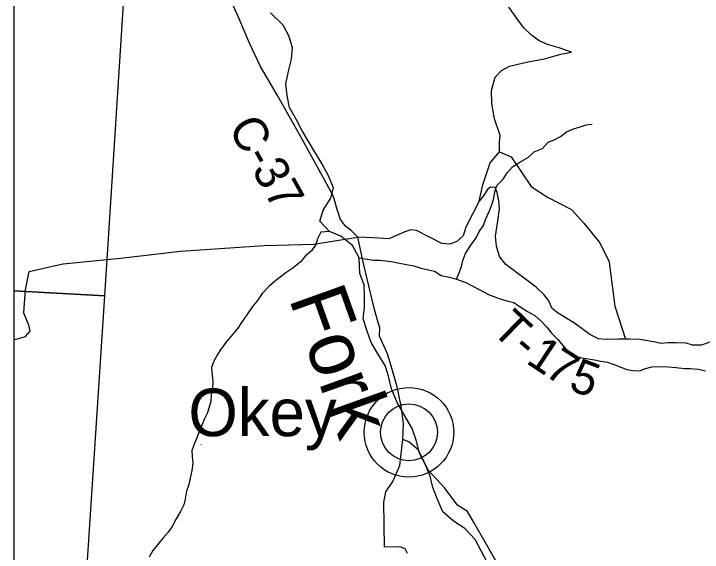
# Model space of a CAD drawing. Extents: x 396.2 to 468.4, y 232.6 to 279.1.
# Drawn here: x 413.851 to 414.996, y 267.141 to 268.036 of the extents above; entities that cross this region are included whole.
import ezdxf

# ---------------------------------------------------------------- set-up
doc = ezdxf.new("R2010")
doc.units = 0
for name, color, linetype in [('Default', 7, 'Continuous'), ('GM_X_County_Road', 7, 'Continuous'), ('GM_X_County_Road_Text', 7, 'Continuous'), ('GM_X_Minor_River', 7, 'Continuous'), ('GM_X_Minor_River_Text', 7, 'Continuous'), ('GM_X_Township_Road', 7, 'Continuous'), ('GM_X_Township_Road_Text', 7, 'Continuous'), ('GM_X_Unincorporated', 7, 'Continuous'), ('GM_X_Unincorporated_Location', 7, 'Continuous'), ('GM_X_Unincorporated_Text', 7, 'Continuous'), ('SH_Cut_Line', 7, 'Continuous'), ('TX_P_1', 7, 'Continuous')]:
    doc.layers.add(name, color=color, linetype=linetype)

msp = doc.modelspace()

# ---------------------------------------------------------------- linework, layer by layer
at = {"layer": 'Default'}
for points in [[(413.8513, 270.6726), (413.8513, 264.4868), (414.0592, 264.474), (414.3542, 264.4559), (414.8754, 264.4239), (414.9163, 265.108), (414.9927, 266.2714), (414.9935, 266.2891), (414.9982, 266.4735), (415.0293, 266.9964), (415.0582, 267.4588), (415.0934, 268.0402), (415.1765, 269.4523), (415.2459, 270.5284), (415.2492, 270.5871), (414.466, 270.6401), (414.1359, 270.6553), (413.8849, 270.6706)], [(413.8513, 268.6118), (413.8513, 267.5757), (414.0029, 267.5669), (414.0685, 268.5986)], [(413.8513, 267.5757), (413.8513, 266.5578), (413.936, 266.5526), (414.0029, 267.5669)]]:
    msp.add_lwpolyline(points, close=True, dxfattribs=at)
at = {"layer": 'GM_X_County_Road'}
msp.add_lwpolyline([(414.5058, 267.1388), (414.5019, 267.1464), (414.4928, 267.1501), (414.4678, 267.1496), (414.4666, 267.2244), (414.4696, 267.2414), (414.4813, 267.2586), (414.4929, 267.2849), (414.498, 267.3281), (414.499, 267.3547), (414.4954, 267.3839), (414.4884, 267.4158), (414.4784, 267.451), (414.4726, 267.4707), (414.4668, 267.4832), (414.4592, 267.4999), (414.4599, 267.5139), (414.4552, 267.5283), (414.4502, 267.5469), (414.4324, 267.6208), (414.4235, 267.6644), (414.4116, 267.6764), (414.4029, 267.6832), (414.3945, 267.6942), (414.3887, 267.7105), (414.3826, 267.7321), (414.368, 267.7601), (414.3286, 267.8312), (414.2896, 267.9001), (414.2616, 267.9481), (414.2433, 267.9871), (414.2225, 268.0352), (414.2091, 268.0647)], dxfattribs=at)
at = {"layer": 'GM_X_Minor_River'}
for points in [[(414.6417, 267.1181), (414.6289, 267.1424), (414.6183, 267.1621), (414.601, 267.1803), (414.5821, 267.1924), (414.5647, 267.2084), (414.5564, 267.2273), (414.5481, 267.2486), (414.5436, 267.2675), (414.536, 267.2865), (414.5255, 267.3055), (414.5202, 267.3275), (414.5134, 267.3464), (414.4892, 267.3889), (414.4794, 267.4124), (414.4742, 267.4336), (414.4689, 267.4511), (414.4576, 267.4693), (414.4455, 267.4898), (414.4387, 267.5087), (414.4319, 267.5292), (414.4342, 267.5482), (414.4342, 267.5664), (414.4335, 267.5853), (414.4267, 267.6043), (414.4252, 267.6301), (414.4146, 267.6506), (414.395, 267.6665), (414.3761, 267.6741), (414.3602, 267.6915), (414.3655, 267.7097), (414.3784, 267.7294), (414.383, 267.7469), (414.3747, 267.7666), (414.3634, 267.7871), (414.3407, 267.825), (414.3301, 267.8425), (414.3211, 267.8599), (414.3098, 267.8804), (414.306, 267.9001), (414.3037, 267.9198), (414.3083, 267.9426), (414.3129, 267.9608), (414.3144, 267.9797), (414.3084, 267.9995), (414.2993, 268.0169), (414.2782, 268.0374)], [(414.5871, 267.5951), (414.5913, 267.6045), (414.5955, 267.6159), (414.5978, 267.6258), (414.6023, 267.6375), (414.6111, 267.6511), (414.6198, 267.6633), (414.6251, 267.6739), (414.6319, 267.6841), (414.6357, 267.6939), (414.6414, 267.7076), (414.6468, 267.7201), (414.6494, 267.7295), (414.6509, 267.7398), (414.6544, 267.7508), (414.665, 267.761), (414.6714, 267.7716), (414.6805, 267.7818), (414.6926, 267.7894), (414.7067, 267.7977), (414.7165, 267.8064), (414.7301, 267.812), (414.7396, 267.8223), (414.7495, 267.8264), (414.7601, 267.8321), (414.7699, 267.8397), (414.7816, 267.8446), (414.793, 267.8483), (414.8028, 267.8514), (414.8127, 267.8525)], [(414.3761, 267.6741), (414.3618, 267.6731), (414.3561, 267.6621), (414.3534, 267.6523), (414.3462, 267.642), (414.3364, 267.6337), (414.3277, 267.6239), (414.3152, 267.6129), (414.3034, 267.6053), (414.2898, 267.5948), (414.2761, 267.583), (414.2644, 267.5713), (414.2564, 267.5596), (414.2481, 267.5497), (414.2386, 267.5357), (414.231, 267.5243), (414.2238, 267.5134), (414.2155, 267.5035), (414.206, 267.4922), (414.1954, 267.4785), (414.1893, 267.4687), (414.184, 267.4585), (414.1802, 267.4478), (414.1813, 267.4357), (414.182, 267.424), (414.1817, 267.4134), (414.1797, 267.4031), (414.179, 267.3914), (414.1763, 267.3819), (414.1729, 267.3717), (414.1676, 267.3615), (414.1509, 267.3192)], [(414.4252, 267.6301), (414.4389, 267.6279), (414.4495, 267.6267), (414.4593, 267.6263), (414.4692, 267.6252), (414.4794, 267.624), (414.4926, 267.6217), (414.5043, 267.6195), (414.5161, 267.6168), (414.5285, 267.613), (414.5406, 267.6103), (414.5505, 267.608), (414.5618, 267.6008), (414.5758, 267.5981), (414.5871, 267.5951), (414.6026, 267.5894), (414.6132, 267.5837), (414.6261, 267.5772), (414.6404, 267.5696), (414.6563, 267.5631), (414.6711, 267.5586), (414.6828, 267.5559), (414.6945, 267.5479), (414.7055, 267.5411), (414.7176, 267.5346), (414.7281, 267.5251), (414.7376, 267.5149), (414.7455, 267.5046), (414.7557, 267.4944), (414.7644, 267.4838), (414.7731, 267.4735), (414.7852, 267.4671), (414.7961, 267.464), (414.8166, 267.4609), (414.8271, 267.4587), (414.8381, 267.4567), (414.8479, 267.4537), (414.8604, 267.4484), (414.8702, 267.4449), (414.8812, 267.443), (414.8914, 267.4423), (414.9017, 267.4464), (414.9122, 267.4491), (414.9247, 267.4498), (414.9395, 267.4494), (414.9524, 267.4482), (414.966, 267.4463), (414.9758, 267.4463), (414.9894, 267.4455), (415.0011, 267.4425)], [(414.1509, 267.3192), (414.1509, 267.3192), (414.1471, 267.3098), (414.1479, 267.3003), (414.149, 267.2889), (414.1472, 267.2768), (414.1445, 267.2639), (414.1423, 267.2537), (414.1385, 267.2427), (414.1362, 267.2294), (414.134, 267.2195), (414.1283, 267.2085), (414.1211, 267.1964), (414.1151, 267.1847), (414.1079, 267.1744), (414.0996, 267.1649), (414.0905, 267.1532), (414.0822, 267.1437), (414.0765, 267.1327)], [(414.1626, 267.3194), (414.1622, 267.3198)]]:
    msp.add_lwpolyline(points, dxfattribs=at)
at = {"layer": 'GM_X_Township_Road'}
for points in [[(414.625, 267.7247), (414.6308, 267.7517), (414.6432, 267.7882), (414.6586, 267.8065), (414.6586, 267.8218), (414.66, 267.8335), (414.6505, 267.8612), (414.6462, 267.8868), (414.6454, 267.9087), (414.6513, 267.9306), (414.6622, 267.9415), (414.6754, 267.9488), (414.706, 267.9561), (414.7338, 267.9613), (414.7608, 267.9686), (414.7783, 267.9722), (414.7581, 267.9795), (414.7383, 267.9848), (414.7244, 267.9908), (414.7118, 268.0007), (414.6993, 268.0126), (414.69, 268.0252), (414.6741, 268.047)], [(414.6586, 267.8065), (414.678, 267.798), (414.7115, 267.7488), (414.7384, 267.7309), (414.7786, 267.7108), (414.7988, 267.6879), (414.8256, 267.6554), (414.8412, 267.6236), (414.8429, 267.6097)], [(414.8719, 267.4949), (414.8681, 267.4949), (414.8565, 267.4949), (414.8361, 267.4944), (414.8235, 267.4955), (414.8091, 267.503), (414.7832, 267.5215), (414.7551, 267.5391), (414.7459, 267.5467), (414.7406, 267.5588), (414.7329, 267.569), (414.7196, 267.5818), (414.669, 267.6191), (414.6587, 267.6327), (414.6537, 267.6498), (414.6521, 267.6665), (414.6557, 267.6919), (414.659, 267.7117), (414.6578, 267.7253), (414.6547, 267.739), (414.6517, 267.7473), (414.6437, 267.748), (414.6388, 267.7438), (414.6316, 267.7327), (414.625, 267.7247), (414.6027, 267.6813), (414.5986, 267.6669), (414.5877, 267.6574), (414.5763, 267.6531), (414.5627, 267.6542), (414.5205, 267.6759), (414.5114, 267.677), (414.5011, 267.6735), (414.4747, 267.662), (414.4485, 267.6638), (414.4235, 267.6644)], [(413.9254, 267.6185), (413.9336, 267.6204), (414.029, 267.6299), (414.1283, 267.6413), (414.2677, 267.6509), (414.3498, 267.6528), (414.4235, 267.6644)], [(413.8682, 267.5381), (413.8678, 267.5392), (413.8709, 267.5772), (413.8767, 267.6075), (413.9254, 267.6185)], [(414.8429, 267.6097), (414.8502, 267.5498), (414.8681, 267.4949)], [(413.8513, 267.4938), (413.8707, 267.4993), (413.8787, 267.5087), (413.8761, 267.5183), (413.8753, 267.5209), (413.8682, 267.5381)], [(415.0584, 267.4583), (415.0421, 267.4649), (415.0337, 267.4762), (415.0222, 267.4895), (415.0135, 267.4917), (414.9942, 267.4851), (414.9798, 267.485), (414.9692, 267.4884), (414.9525, 267.489), (414.9392, 267.489), (414.9275, 267.4881), (414.9149, 267.4907), (414.8922, 267.4948), (414.8748, 267.4949), (414.8719, 267.4949)], [(414.8616, 266.822), (414.863, 266.8413), (414.8629, 266.8565), (414.8605, 266.8683), (414.8537, 266.877), (414.8427, 266.8961), (414.838, 266.9043), (414.8076, 266.9797), (414.7865, 267.0203), (414.7654, 267.0555), (414.7361, 267.0878), (414.7198, 267.1002), (414.7012, 267.108), (414.6587, 267.1162), (414.6154, 267.1914), (414.6055, 267.2085), (414.5891, 267.219), (414.5678, 267.2473), (414.5399, 267.2772), (414.5242, 267.3108), (414.5082, 267.3244), (414.498, 267.3281)]]:
    msp.add_lwpolyline(points, dxfattribs=at)
at = {"layer": 'GM_X_Unincorporated'}
for radius in [0.0744, 0.0472]:
    msp.add_circle((414.5082, 267.3403), radius, dxfattribs=at)
at = {"layer": 'GM_X_Unincorporated_Location'}
msp.add_line((414.5082, 267.3403), (414.5082, 267.3403), dxfattribs=at)
at = {"layer": 'SH_Cut_Line'}
msp.add_lwpolyline([(413.8513, 270.6726), (413.8513, 264.2582), (416.1109, 264.2582), (415.3533, 264.289), (414.8684, 264.3083), (414.8754, 264.4239), (414.9163, 265.108), (414.9927, 266.2714), (414.9935, 266.2891), (414.9982, 266.4735), (415.0293, 266.9964), (415.0582, 267.4588), (415.0934, 268.0402), (415.1765, 269.4523), (415.2459, 270.5284), (415.2492, 270.5871), (414.466, 270.6401), (414.1359, 270.6553), (413.8849, 270.6706)], close=True, dxfattribs=at)
at = {"layer": 'TX_P_1'}
msp.add_line((413.8513, 277.8582), (413.8513, 264.2582), dxfattribs=at)

# ---------------------------------------------------------------- texts
at = {"layer": 'GM_X_County_Road_Text'}
msp.add_text('C-37', height=0.05682, rotation=299.1887, dxfattribs=at).set_placement((414.2069, 267.847))
at = {"layer": 'GM_X_Minor_River_Text'}
msp.add_text('Fork', height=0.09469, rotation=289.6605, dxfattribs=at).set_placement((414.308, 267.5632))
at = {"layer": 'GM_X_Township_Road_Text'}
for s, rotation, p in [('T', 315.9016, (414.6436, 267.5083)), ('-', 319.7622, (414.6772, 267.4759)), ('1', 326.4872, (414.7008, 267.4565)), ('7', 327.3258, (414.7308, 267.4367)), ('5', 339.0958, (414.7716, 267.412))]:
    msp.add_text(s, height=0.0568, rotation=rotation, dxfattribs=at).set_placement(p)
at = {"layer": 'GM_X_Unincorporated_Text'}
msp.add_text('Okey', height=0.07898, rotation=0, dxfattribs=at).set_placement((414.1416, 267.3339))

doc.saveas('drawing.dxf')
